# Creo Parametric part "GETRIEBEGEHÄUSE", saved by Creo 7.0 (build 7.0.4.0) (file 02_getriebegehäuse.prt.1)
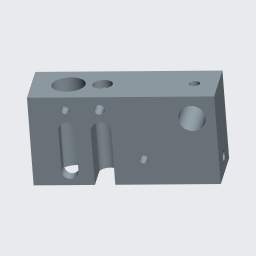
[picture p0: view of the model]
Units: millimeter Kilogram Sec (mmKs); MM, KILOGRAM, SECS
Materials in the file: STAHL

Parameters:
  PTC_MATERIAL_NAME = "STAHL"
  WERKSTOFF = "Stahl"
  ERSTELLER = "ARINDA"
  BENENNUNG = "XXX"
  TEILETYP = "K"
  PTC_MASTER_MATERIAL = "STAHL"
  SCHRAUBEN_GROESSE = "M4x.7"
  METRISCH = "JA"

Other parameters: MASSE, STEIGUNG, BOHR_DURCHM, GEWINDEDURCHMESSER, GEWINDEGÄNGE_PRO_INCH, GEWINDETIEFE, GEWINDELÄNGE, ANSENKDURCHMESSER, ANSENKTIEFE, KEGELSENKER_DURCHMESSER, SENKWINKEL

Created from: KOPF.PRT

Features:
  1. coordinate system
  2. datum plane "RECHTS_Y-Z"
  3. datum plane "OBEN_X-Z"
  4. datum plane "VORNE_X-Y"
  5. datum axis
  6. datum axis
  7. datum axis
  8. datum point "PNT0"
  9. protrusion
  10. hole "Bohrung 1"
  11. hole "Bohrung 2"
  12. hole "Bohrung 3"
  13. hole "Bohrung 4"
  14. hole "Bohrung 5"
  15. hole "Bohrung 6"
  16. hole "Bohrung 7"
  17. extruded cut "Profil 2"
  18. hole "Bohrung 8"
  19. extruded cut "Profil 3"
  20. extruded cut "Profil 4"
  21. hole "Bohrung 9"

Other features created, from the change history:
  planar section "A"

Other named items: GRUNDKÖRPER, STÄNDERBOHRUNG, FIXIERUNG_STÄNDER, UMLENKROLLE, FIXIERUNG_UMLENKROLLE, SPINDEL, FIXIERUNG_SPINDELLAGER, FÜHRUNG_RIEMENSCHEIBE, FENSTER_SPINDEL, FEDERBOHRUNG, FEDERFENSTER, FEDERAUFHÄNGUNG, HEBELBOHRUNG, A_X, A_Y, A_Z, CS0

Layers: 01_ACHSEN, 01_ACHSEN_STD, 01_EBENEN_STD, 01_KOORDSYS_STD, 01_PUNKTE_STD, GEWINDE, SAMMELFLÄCHEN, VOLUMENGEOMETRIE

Notes: M4x.7 | GEWINDEBOHREN | 7.920 |  BOHREN (  | 3.300 | DURCH |   -(  |  ) BOHRUNG | M3x.5 | GEWINDEBOHREN | 6.000 |  BOHREN (  | 2.500 | DURCH |   -(  |  ) BOHRUNG | M3x.5 | GEWINDEBOHREN | DURCH |  BOHREN (  | 2.500 | DURCH |   -(  |  ) BOHRUNG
